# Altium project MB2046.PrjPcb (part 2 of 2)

## Sheet FDCAN.SchDoc: FDCAN
size A4; Date: Not used; ApprovedBy: Not used; CheckedBy: Not used; Author: Not used; CompanyName: STMicroelectronics; DrawnBy: Not used; Engineer: Not used; Organization: Not used; Address1: Not used; Address2: Not used; Address3: Not used; Address4: Not used; DocumentNumber: Not used; Revision: Not used; SheetNumber: 6; SheetTotal: 8
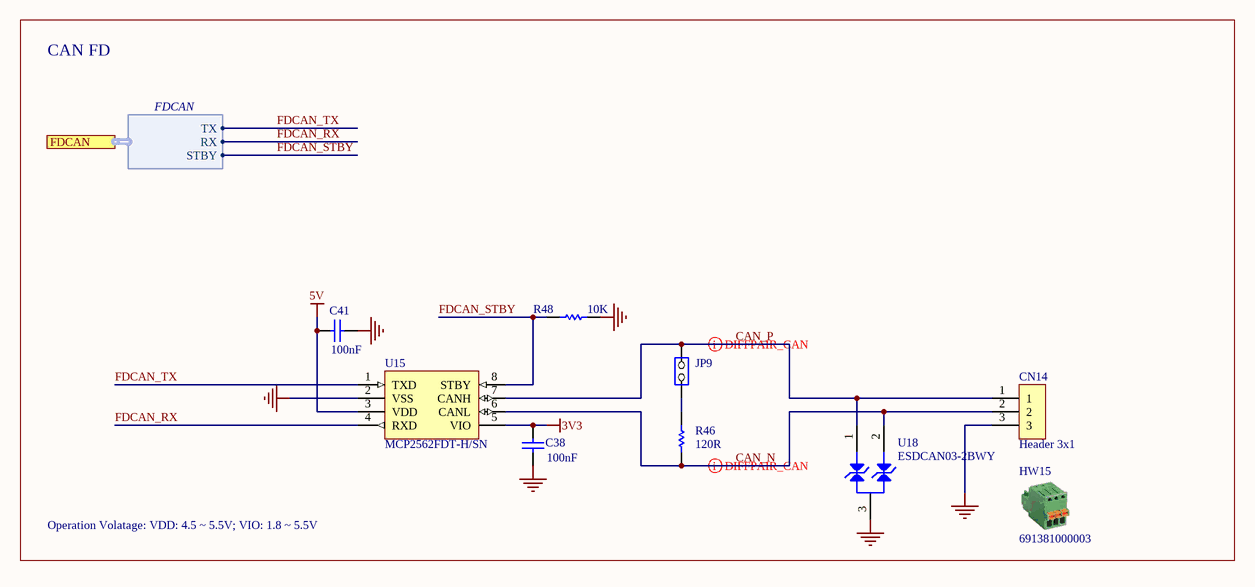
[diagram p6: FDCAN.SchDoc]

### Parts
C38  value 100nF  [C0402]  (hidden comment: Capacitor)
C41  value 100nF  [C0402]  (hidden comment: Capacitor)
CN14  Header 3x1  [CON_WE-691382010003]
HW15  691381000003
JP9  Jumper_Header 2x1  [CON_SAMTEC_TSW-102-07-G-S]  (value not drawn)
R46  value 120R  [R0402]  (hidden comment: Resistor)
R48  value 10K  [R0402]  (hidden comment: Resistor)
U15  value MCP2562FDT-H/SN  [ICC_SO8_5X4_P127]  (hidden comment: MCP2562FD)
U18  value ESDCAN03-2BWY  [DIO_SOT323]  (hidden comment: ESD-TRANSIL-DUAL-BIDIR)

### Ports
FDCAN (harness FDCAN)

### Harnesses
FDCAN: TX, RX, STBY

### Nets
3V3: C38.1 U15.5(VIO)
5V: C41.1 U15.3(VDD)
GND: C38.2 C41.2 CN14.3 R48.2 U15.2(VSS) U18.3
CAN_N: CN14.2 R46.1 U15.6(CANL) U18.2
CAN_P: CN14.1 JP9.2(NO) U15.7(CANH) U18.1
FDCAN_RX: U15.4(RXD) ; port FDCAN.RX
FDCAN_STBY: R48.1 U15.8(STBY) ; port FDCAN.STBY
FDCAN_TX: U15.1(TXD) ; port FDCAN.TX
NetJP9_1: JP9.1(COMMON) R46.2

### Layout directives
differential pair: CAN_N, CAN_P

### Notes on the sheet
- CAN FD
- Operation Volatage: VDD: 4.5 ~ 5.5V; VIO: 1.8 ~ 5.5V

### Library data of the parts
C38 C41 = MCD-00006: Capacitor, MLCC, 100nF, 16V, X7R, +/-10%, 0402, T=0.5mm; Manufacturer_Part_Number: CC0402KRX7R7BB104; Manufacturer: YAGEO; Part_Preference: Recommended; Partial_Alternate_Internal_Part_Number: MCD-03299; Order_Code_RS: 9402047; Component_Country_Of_Origin: China; ShowFields: YES; ID: 2474
CN14 = MCD-04055: Header, 3x1, 2.5mm, RA, TH, T=8.1mm/3.5mm; Part_Type: Connector; Part_Preference: Recommended; Manufacturer: WURTH ELEKTRONIK; Manufacturer_Part_Number: 691382010003; Order_Code_RS: 163-1789; ShowFields: YES; ID: 6171; Component_Country_Of_Origin: China
HW15 = MCD-04056: Pluggable Terminal Block, 2.5mm, 3 Ways; Part_Type: Misc; Part_Preference: Recommended; Manufacturer: WURTH ELEKTRONIK; Order_Code_RS: 122-4916; ShowFields: YES; ID: 6172; Component_Country_Of_Origin: China
JP9 = MCD-00045: Header, 2x1, 2.54mm, VR, TH, T=5.84mm/2.54mm; Manufacturer_Part_Number: TSW-102-07-G-S; Manufacturer: SAMTEC; Part_Type: Connector; Part_Preference: Recommended; Full_Alternate_Internal_Part_Number: MCD-02390; Partial_Alternate_Internal_Part_Number: MCD-02957, MCD-03720, MCD-04249; Order_Code_RS: 2505044; Component_Country_Of_Origin: China, Costa Rica, Malaysia, USA, Vietnam; ShowFields: YES; ID: 2545
R46 = MCD-00194: Resistor, 120R, 0402, +/-1%, 1/16W; Manufacturer_Part_Number: RC0402FR-07120RL; Manufacturer: YAGEO; Part_Preference: Recommended; Component_Country_Of_Origin: China; ShowFields: YES; ID: 2674
R48 = MCD-00053: Resistor, 10K, 0402, +/-1%, 1/16W; Manufacturer_Part_Number: RC0402FR-0710KL; Manufacturer: YAGEO; BMS_Part_Number: 9131590; Part_Preference: Recommended; Order_Code_RS: 9239359; Component_Country_Of_Origin: China; ShowFields: YES; ID: 2539
U15 = MCD-00129: IC, High-Speed CAN flexible data rate transceiver; Manufacturer: MICROCHIP; Part_Preference: Recommended; Component_Country_Of_Origin: Unknown; ShowFields: YES; ID: 2737
U18 = MCD-01228: Diode, ESD TVS, 24V, 10nA, 29V7, SOT323-3; BMS_Part_Number: 9179049; Manufacturer: STMICROELECTRONICS; Part_Preference: Recommended; Manufacturer_HQ_COO: EU; Order_Code_RS: 124-1110; Component_Country_Of_Origin: China; ShowFields: YES; ID: 3269

## Sheet Connectors.SchDoc: Connectors
size A4; Date: Not used; ApprovedBy: Not used; CheckedBy: Not used; Author: Not used; CompanyName: STMicroelectronics; DrawnBy: Not used; Engineer: Not used; Organization: Not used; Address1: Not used; Address2: Not used; Address3: Not used; Address4: Not used; DocumentNumber: 5; Revision: Not used; SheetNumber: 4; SheetTotal: 8
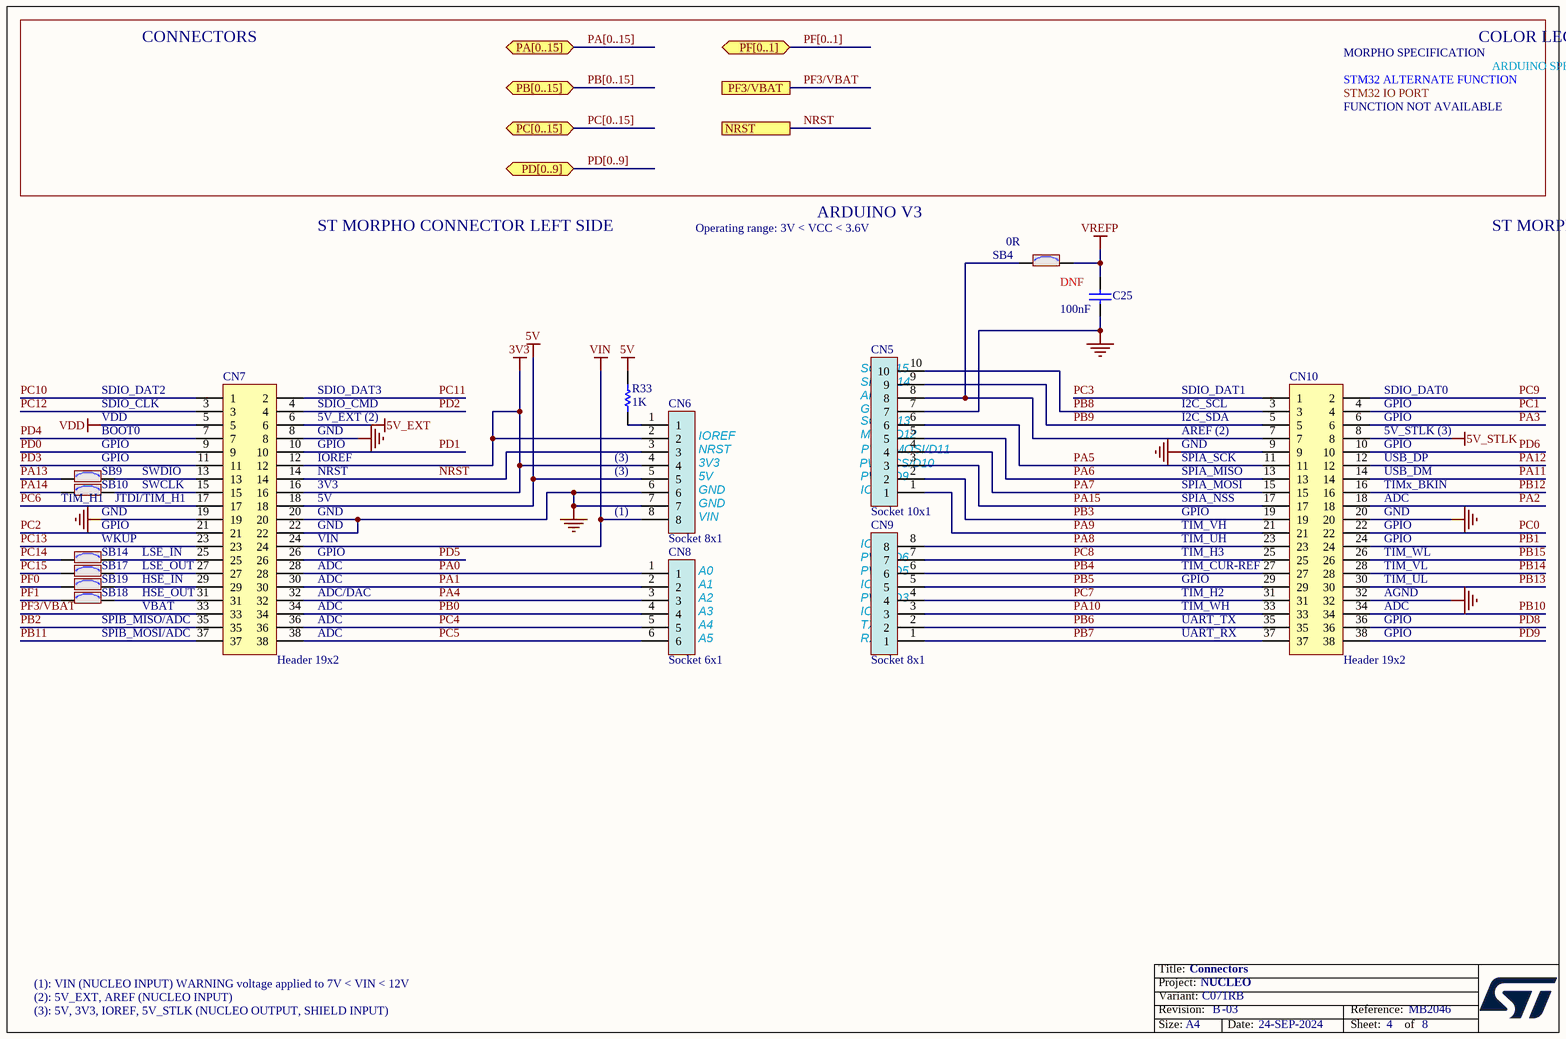
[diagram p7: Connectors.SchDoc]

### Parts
C25  value 100nF  [C0402]  (hidden comment: Capacitor)
CN5  Socket 10x1  [CON_SAMTEC_SSW-110-01-X-S]
CN6  Socket 8x1  [CON_SAMTEC_SSW-108-01-X-S]
CN7  Header 19x2  [CON_SAMTEC_TSW-119-09-X-D]
CN8  Socket 6x1  [CON_SAMTEC_SSW-106-01-X-S]
CN9  Socket 8x1  [CON_SAMTEC_SSW-108-01-X-S]
CN10  Header 19x2  [CON_SAMTEC_TSW-119-09-X-D]
R33  value 1K  [R0402]  (hidden comment: Resistor)
SB4  value 0R  [SOLDER-BRIDGE_R0603-0R]  (hidden comment: SB_ON)
SB9  SB_ON  [SOLDER-BRIDGE_R0603-0R]  (value not drawn)
SB10  SB_ON  [SOLDER-BRIDGE_R0603-0R]  (value not drawn)
SB14  SB_ON  [SOLDER-BRIDGE_R0603-0R]  (value not drawn)
SB17  SB_ON  [SOLDER-BRIDGE_R0603-0R]  (value not drawn)
SB18  SB_ON  [SOLDER-BRIDGE_R0603-0R]  (value not drawn)
SB19  SB_ON  [SOLDER-BRIDGE_R0603-0R]  (value not drawn)

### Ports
NRST, PA[0..15] (bidir), PB[0..15] (bidir), PC[0..15] (bidir), PD[0..9] (bidir), PF3/VBAT, PF[0..1] (bidir)

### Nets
3V3: CN6.2 CN6.4 CN7.12 CN7.16
5V: CN6.5 CN7.18 R33.1
5V_EXT: CN7.6
5V_STLK: CN10.8
GND: C25.2 CN5.7 CN6.6 CN6.7 CN7.8 CN7.19 CN7.20 CN7.22 CN10.9 CN10.20 CN10.32
VDD: CN7.5
VIN: CN6.8 CN7.24
VREFP: C25.1 SB4.2
NRST: CN6.3 CN7.14 ; port NRST
PA0: CN7.28 CN8.1
PA1: CN7.30 CN8.2
PA2: CN10.18  [project net MCU.VCP_TX]
PA3: CN10.6  [project net MCU.VCP_RX]
PA4: CN7.32 CN8.3
PA5: CN5.6 CN10.11
PA6: CN5.5 CN10.13
PA7: CN5.4 CN10.15
PA8: CN9.8 CN10.23
PA9: CN5.1 CN10.21
PA10: CN9.3 CN10.33
PA11: CN10.14
PA12: CN10.12
PA13: SB9.1  [project net MCU.SWDIO]
PA14: SB10.1  [project net MCU.SWCLK]
PA15: CN5.3 CN10.17
PB0: CN7.34 CN8.4
PB1: CN10.24
PB2: CN7.35
PB3: CN5.2 CN10.19  [project net MCU.SWO]
PB4: CN9.6 CN10.27
PB5: CN9.5 CN10.29
PB6: CN9.2 CN10.35
PB7: CN9.1 CN10.37
PB8: CN5.10 CN10.3
PB9: CN5.9 CN10.5
PB10: CN10.34
PB11: CN7.37
PB12: CN10.16
PB13: CN10.30
PB14: CN10.28
PB15: CN10.26
PC0: CN10.22
PC1: CN10.4
PC2: CN7.21
PC3: CN10.1
PC4: CN7.36 CN8.5
PC5: CN7.38 CN8.6
PC6: CN7.17
PC7: CN9.4 CN10.31
PC8: CN9.7 CN10.25
PC9: CN10.2
PC10: CN7.1
PC11: CN7.2
PC12: CN7.3
PC13: CN7.23
PC14: SB14.1
PC15: SB17.1
PD0: CN7.9
PD1: CN7.10
PD2: CN7.4
PD3: CN7.11
PD4: CN7.7
PD5: CN7.26
PD6: CN10.10
PD8: CN10.36
PD9: CN10.38
PF0: SB19.1
PF1: SB18.1
PF3/VBAT: CN7.33 ; port PF3/VBAT
NetCN5_8: CN5.8 CN10.7 SB4.1
NetCN6_1: CN6.1 R33.2
NetCN7_13: CN7.13 SB9.2
NetCN7_15: CN7.15 SB10.2
NetCN7_25: CN7.25 SB14.2
NetCN7_27: CN7.27 SB17.2
NetCN7_29: CN7.29 SB19.2
NetCN7_31: CN7.31 SB18.2

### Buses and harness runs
bus PA[0..15] = port PA[0..15]
bus PB[0..15] = port PB[0..15]
bus PC[0..15] = port PC[0..15]
bus PD[0..9] = port PD[0..9]
bus PF[0..1] = port PF[0..1]

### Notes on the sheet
- CONNECTORS
- COLOR LEGEND
- MORPHO SPECIFICATION
- STM32 ALTERNATE FUNCTION
- STM32 IO PORT
- FUNCTION NOT AVAILABLE
- ARDUINO SPECIFICATION
- ST MORPHO CONNECTOR LEFT SIDE
- Operating range: 3V < VCC < 3.6V
- ARDUINO V3
- ST MORPHO CONNECTOR RIGHT SIDE
- DNF
- (near CN5) SDA/D14
- (near CN5) SCL/D15
- BOOT0
- GPIO
- VDD
- SDIO_DAT2
- SDIO_CLK
- (near CN7) GPIO
- (near CN7) 5V_EXT (2)
- (near CN7) GND
- (near CN7) SDIO_DAT3
- (near CN7) SDIO_CMD
- (near CN6) IOREF
- (near CN6) NRST
- (near CN5) SCK/D13
- (near CN5) MISO/D12
- (near CN5) AREF
- (near CN5) GND
- (near CN5) PWM/MOSI/D11
- I2C_SCL
- I2C_SDA
- AREF (2)
- GND
- (near CN10) SDIO_DAT1
- (near CN10) GPIO
- (near CN10) 5V_STLK (3)
- (near CN10) SDIO_DAT0
- (near SB10) TIM_H1
- (near SB9) GPIO
- (near SB10) GND
- JTDI/TIM_H1
- SWDIO
- SWCLK
- (near CN7) IOREF
- (near CN7) 3V3
- (near CN7) 5V
- (near CN7) NRST
- (near CN6) (1)
- (3)
- (near CN6) 3V3
- (near CN6) 5V
- (near CN6) GND
- (near CN6) VIN
- (near CN5) PWM/CS/D10
- (near CN5) IO/D8
- (near CN5) PWM/D9
- SPIA_SCK
- (near CN10) SPIA_MISO
- (near CN10) SPIA_MOSI
- SPIA_NSS
- (near CN10) USB_DP
- (near CN10) USB_DM
- (near CN10) TIMx_BKIN
- (near CN10) ADC
- (near CN10) GND
- (near SB14) WKUP
- LSE_IN
- LSE_OUT
- HSE_IN
- (near CN7) VIN
- (near CN7) ADC
- (near CN8) A0
- (near CN8) A1
- (near CN9) IO/D4
- (near CN9) PWM/D5
- (near CN9) PWM/D6
- IO/D7
- TIM_VH
- TIM_UH
- TIM_H3
- (near CN10) TIM_CUR-REF
- (near CN10) TIM_WL
- (near CN10) TIM_VL
- (near CN10) TIM_UL
- (near SB18) SPIB_MISO/ADC
- SPIB_MOSI/ADC
- HSE_OUT
- VBAT
- (near CN7) ADC/DAC
- (near CN8) A2
- (near CN8) A3
- (near CN8) A4
- (near CN8) A5
- (near CN9) RX/D0
- (near CN9) TX/D1
- (near CN9) IO/D2
- (near CN9) PWM/D3
- TIM_H2
- TIM_WH
- UART_TX
- UART_RX
- (near CN10) AGND
- (1): VIN (NUCLEO INPUT) WARNING voltage applied to 7V < VIN < 12V
- (2): 5V_EXT, AREF (NUCLEO INPUT)
- (3): 5V, 3V3, IOREF, 5V_STLK (NUCLEO OUTPUT, SHIELD INPUT)

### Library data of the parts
C25 = MCD-00006: as C38 on sheet FDCAN
CN5 = MCD-02080: Socket, 10x1, 2.54mm, VR, TH, T=8.51/2.64mm; Part_Type: Connector; Part_Preference: Recommended; Manufacturer: SAMTEC; Manufacturer_Part_Number: SSW-110-01-G-S; Partial_Alternate_Internal_Part_Number: MCD-03160; Order_Code_RS: 765-5736; Component_Country_Of_Origin: China, Costa Rica, Malaysia, USA, Vietnam; ShowFields: YES; ID: 4180
CN6 CN9 = MCD-01743: Socket, 8x1, 2.54mm, VR, TH, T=8.51/2.64mm; Part_Type: Connector; Part_Preference: Recommended; Manufacturer: SAMTEC; Manufacturer_Part_Number: SSW-108-01-G-S; Partial_Alternate_Internal_Part_Number: MCD-03161; Order_Code_RS: 765-5698; Component_Country_Of_Origin: China, Costa Rica, Malaysia, USA, Vietnam; ShowFields: YES; ID: 3843
CN7 CN10 = MCD-00213: Header, 19x2, 2.54mm, VR, TH, T=5.84mm/10.16mm; Part_Type: Connector; Part_Preference: Recommended; Manufacturer: SAMTEC; Manufacturer_Part_Number: TSW-119-09-G-D; Partial_Alternate_Internal_Part_Number: MCD-03736, MCD-03787; Component_Country_Of_Origin: China, Costa Rica, Malaysia, USA, Vietnam; ShowFields: YES; ID: 2656
CN8 = MCD-02079: Socket, 6x1, 2.54mm, VR, TH, T=8.51/2.64mm; Part_Type: Connector; Part_Preference: Recommended; Manufacturer: SAMTEC; Manufacturer_Part_Number: SSW-106-01-G-S; Partial_Alternate_Internal_Part_Number: MCD-03162, MCD-04189; Order_Code_RS: 765-5666; Component_Country_Of_Origin: China, Costa Rica, Malaysia, USA, Vietnam; ShowFields: YES; ID: 4179
R33 = MCD-00061: Resistor, 1K, 0402, +/-1%,1/16W; Manufacturer_Part_Number: RC0402FR-071KL; Manufacturer: YAGEO; Part_Preference: Recommended; Order_Code_RS: 9239235; Component_Country_Of_Origin: China; ShowFields: YES; ID: 2532
SB4 = MCD-00071: Resistor, 0R, SB0603, 5%, 0.1W; Manufacturer_Part_Number: RC0603JR-070RL; Manufacturer: YAGEO; Part_Preference: Recommended; Manufacturer_HQ_COO: Unknown; Order_Code_RS: 199-5647; ShowFields: YES; ID: 2521; Component_Country_Of_Origin: China
SB9 SB10 SB14 SB17 = MCD-00071: Resistor, 0R, SB0603, 5%, 0.1W; Manufacturer_Part_Number: RC0603JR-070RL; Manufacturer: YAGEO; Part_Preference: Recommended; Manufacturer_HQ_COO: Unknown; Component_Country_Of_Origin: China; ShowFields: YES; ID: 2521; Order_Code_RS: 199-5647
SB18 SB19 = MCD-00071: Resistor, 0R, SB0603, 5%, 0.1W; Manufacturer_Part_Number: RC0603JR-070RL; Manufacturer: YAGEO; Part_Preference: Recommended; Manufacturer_HQ_COO: Unknown; ShowFields: YES; ID: 2521; Order_Code_RS: 199-5647; Component_Country_Of_Origin: China

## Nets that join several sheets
3V3: Power (JP5.2 R15.2 R16.2 SB2.2), STM32_microcontroller_IOs (B3.2 B3.4 R34.2), STLINK_V2EC (CN4.3 JP8.1 U8.4), FDCAN (C38.1 U15.5), Connectors (CN6.2 CN6.4 CN7.12 CN7.16)
5V: Power (9 pins), STLINK_V2EC (D2.1 R9.2), FDCAN (C41.1 U15.3), Connectors (CN6.5 CN7.18 R33.1)
5V_EXT: Power (JP1.5), Connectors (CN7.6)
5V_STLK: Power (JP1.1), STLINK_V2EC (C1.2 U1.1), Connectors (CN10.8)
5V_USB: Power (JP1.7), USB-C_Device (5 pins)
GND: Power (17 pins), STM32_microcontroller_IOs (26 pins), STLINK_V2EC (58 pins), USB-C_Device (21 pins), FDCAN (6 pins), Connectors (11 pins)
VDD: Power (JP5.1), STM32_microcontroller_IOs (6 pins), Connectors (CN7.5)
VIN: Power (C24.2 U10.3), Connectors (CN6.8 CN7.24)
VREFP: STM32_microcontroller_IOs (C30.2 C31.1 R42.2 U14.7), Connectors (C25.1 SB4.2)
FDCAN_RX: STM32_microcontroller_IOs (SB11.2), FDCAN (U15.4)
FDCAN_STBY: STM32_microcontroller_IOs (SB13.2), FDCAN (R48.1 U15.8)
FDCAN_TX: STM32_microcontroller_IOs (SB12.2), FDCAN (U15.1)
MCU.MCO: STM32_microcontroller_IOs (SB20.1), STLINK_V2EC (C10.2 R23.2 TP2.1)
MCU.SWCLK: STM32_microcontroller_IOs (SB3.1 U14.46), STLINK_V2EC (CN4.6 JP4.1 R22.1 U4.1), Connectors (SB10.1)
MCU.SWDIO: STM32_microcontroller_IOs (U14.45), STLINK_V2EC (CN4.4 JP2.1 U4.5), Connectors (SB9.1)
MCU.SWO: STM32_microcontroller_IOs (U14.57), STLINK_V2EC (CN4.8 JP6.1 U4.3), Connectors (CN5.2 CN10.19)
MCU.VCP_RX: STM32_microcontroller_IOs (U14.20), STLINK_V2EC (CN4.13 R26.2 U8.3), Connectors (CN10.6)
MCU.VCP_TX: STM32_microcontroller_IOs (U14.19), STLINK_V2EC (CN4.14 R27.2 U8.1), Connectors (CN10.18)
NRST: STM32_microcontroller_IOs (5 pins), STLINK_V2EC (CN4.12 JP7.1 U8.5), Connectors (CN6.3 CN7.14)
PA0: STM32_microcontroller_IOs (U14.17), Connectors (CN7.28 CN8.1)
PA1: STM32_microcontroller_IOs (U14.18), Connectors (CN7.30 CN8.2)
PA4: STM32_microcontroller_IOs (U14.21), Connectors (CN7.32 CN8.3)
PA5: Power (SB1.2), STM32_microcontroller_IOs (U14.22), Connectors (CN5.6 CN10.11)
PA6: STM32_microcontroller_IOs (U14.23), Connectors (CN5.5 CN10.13)
PA7: STM32_microcontroller_IOs (U14.24), Connectors (CN5.4 CN10.15)
PA8: STM32_microcontroller_IOs (U14.36), Connectors (CN9.8 CN10.23)
PA9: STM32_microcontroller_IOs (U14.37), Connectors (CN5.1 CN10.21)
PA10: STM32_microcontroller_IOs (U14.42), Connectors (CN9.3 CN10.33)
PA11: STM32_microcontroller_IOs (SB7.1), Connectors (CN10.14)
PA12: STM32_microcontroller_IOs (SB6.1), Connectors (CN10.12)
PA15: STM32_microcontroller_IOs (U14.47), Connectors (CN5.3 CN10.17)
PB0: STM32_microcontroller_IOs (U14.27), Connectors (CN7.34 CN8.4)
PB1: STM32_microcontroller_IOs (U14.28), Connectors (CN10.24)
PB2: STM32_microcontroller_IOs (U14.29), Connectors (CN7.35)
PB4: STM32_microcontroller_IOs (U14.58), Connectors (CN9.6 CN10.27)
PB5: STM32_microcontroller_IOs (U14.59), Connectors (CN9.5 CN10.29)
PB6: STM32_microcontroller_IOs (U14.60), Connectors (CN9.2 CN10.35)
PB7: STM32_microcontroller_IOs (U14.61), Connectors (CN9.1 CN10.37)
PB8: STM32_microcontroller_IOs (U14.62), Connectors (CN5.10 CN10.3)
PB9: STM32_microcontroller_IOs (U14.63), Connectors (CN5.9 CN10.5)
PB10: STM32_microcontroller_IOs (U14.30), Connectors (CN10.34)
PB11: STM32_microcontroller_IOs (U14.31), Connectors (CN7.37)
PB12: STM32_microcontroller_IOs (U14.32), Connectors (CN10.16)
PB13: STM32_microcontroller_IOs (U14.33), Connectors (CN10.30)
PB14: STM32_microcontroller_IOs (U14.34), Connectors (CN10.28)
PB15: STM32_microcontroller_IOs (U14.35), Connectors (CN10.26)
PC0: STM32_microcontroller_IOs (U14.13), USB-C_Device (R39.2 R40.1), Connectors (CN10.22)
PC1: STM32_microcontroller_IOs (U14.14), Connectors (CN10.4)
PC2: STM32_microcontroller_IOs (U14.15), Connectors (CN7.21)
PC3: STM32_microcontroller_IOs (U14.16), Connectors (CN10.1)
PC4: STM32_microcontroller_IOs (U14.25), Connectors (CN7.36 CN8.5)
PC5: STM32_microcontroller_IOs (U14.26), Connectors (CN7.38 CN8.6)
PC6: STM32_microcontroller_IOs (U14.38), Connectors (CN7.17)
PC7: STM32_microcontroller_IOs (U14.39), Connectors (CN9.4 CN10.31)
PC8: STM32_microcontroller_IOs (U14.48), Connectors (CN9.7 CN10.25)
PC9: Power (LD2.2), STM32_microcontroller_IOs (U14.49), Connectors (CN10.2)
PC10: STM32_microcontroller_IOs (U14.64), Connectors (CN7.1)
PC11: STM32_microcontroller_IOs (U14.1), Connectors (CN7.2)
PC12: STM32_microcontroller_IOs (U14.2), Connectors (CN7.3)
PC13: STM32_microcontroller_IOs (SB15.2 U14.3), Connectors (CN7.23)
PC14: STM32_microcontroller_IOs (R35.2 U14.4), Connectors (SB14.1)
PC15: STM32_microcontroller_IOs (R36.2 U14.5), Connectors (SB17.1)
PD0: STM32_microcontroller_IOs (SB11.1 U14.50), Connectors (CN7.9)
PD1: STM32_microcontroller_IOs (SB12.1 U14.51), Connectors (CN7.10)
PD2: STM32_microcontroller_IOs (SB13.1 U14.52), Connectors (CN7.4)
PD3: STM32_microcontroller_IOs (U14.53), Connectors (CN7.11)
PD4: STM32_microcontroller_IOs (U14.54), Connectors (CN7.7)
PD5: STM32_microcontroller_IOs (U14.55), Connectors (CN7.26)
PD6: STM32_microcontroller_IOs (U14.56), Connectors (CN10.10)
PD8: STM32_microcontroller_IOs (SB8.1 U14.40), Connectors (CN10.36)
PD9: STM32_microcontroller_IOs (C26.2 C43.2 SB5.1 U14.41), Connectors (CN10.38)
PF0: STM32_microcontroller_IOs (R37.2 SB20.2 U14.10), Connectors (SB19.1)
PF1: STM32_microcontroller_IOs (R38.2 U14.11), Connectors (SB18.1)
PF3/VBAT: STM32_microcontroller_IOs (C37.1 SB16.2 U14.6), Connectors (CN7.33)
USB.D_N: STM32_microcontroller_IOs (SB7.2 U14.43), USB-C_Device (CN13.A7 CN13.B7 U16.3 U16.4)
USB.D_P: STM32_microcontroller_IOs (SB6.2 U14.44), USB-C_Device (CN13.A6 CN13.B6 U16.1 U16.6)

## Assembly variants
C071RB: not fitted C10 C25 C26 C29 C37 C38 C41 C43 CN11 CN14 HW7 HW15 JP9 R18 R34 R41 R46 R48 SB4 SB5 SB6 SB7 SB8 SB9 SB10 SB11 SB12 SB13 SB14 SB16 SB17 SB18 SB19 SB20 U15 U18
C092RC_S: not fitted C10 C25 C26 C29 C37 C39 C40 C42 C43 CN11 CN13 R18 R34 R39 R40 R41 R43 R44 R45 R47 SB4 SB5 SB8 SB9 SB10 SB14 SB16 SB17 SB18 SB19 SB20 TP5 U16 U17 U19
C092RC: not fitted C10 C25 C26 C29 C37 C39 C40 C42 C43 CN11 CN13 HW7 R18 R34 R39 R40 R41 R43 R44 R45 R47 SB4 SB5 SB8 SB9 SB10 SB14 SB16 SB17 SB18 SB19 SB20 TP5 U16 U17 U19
